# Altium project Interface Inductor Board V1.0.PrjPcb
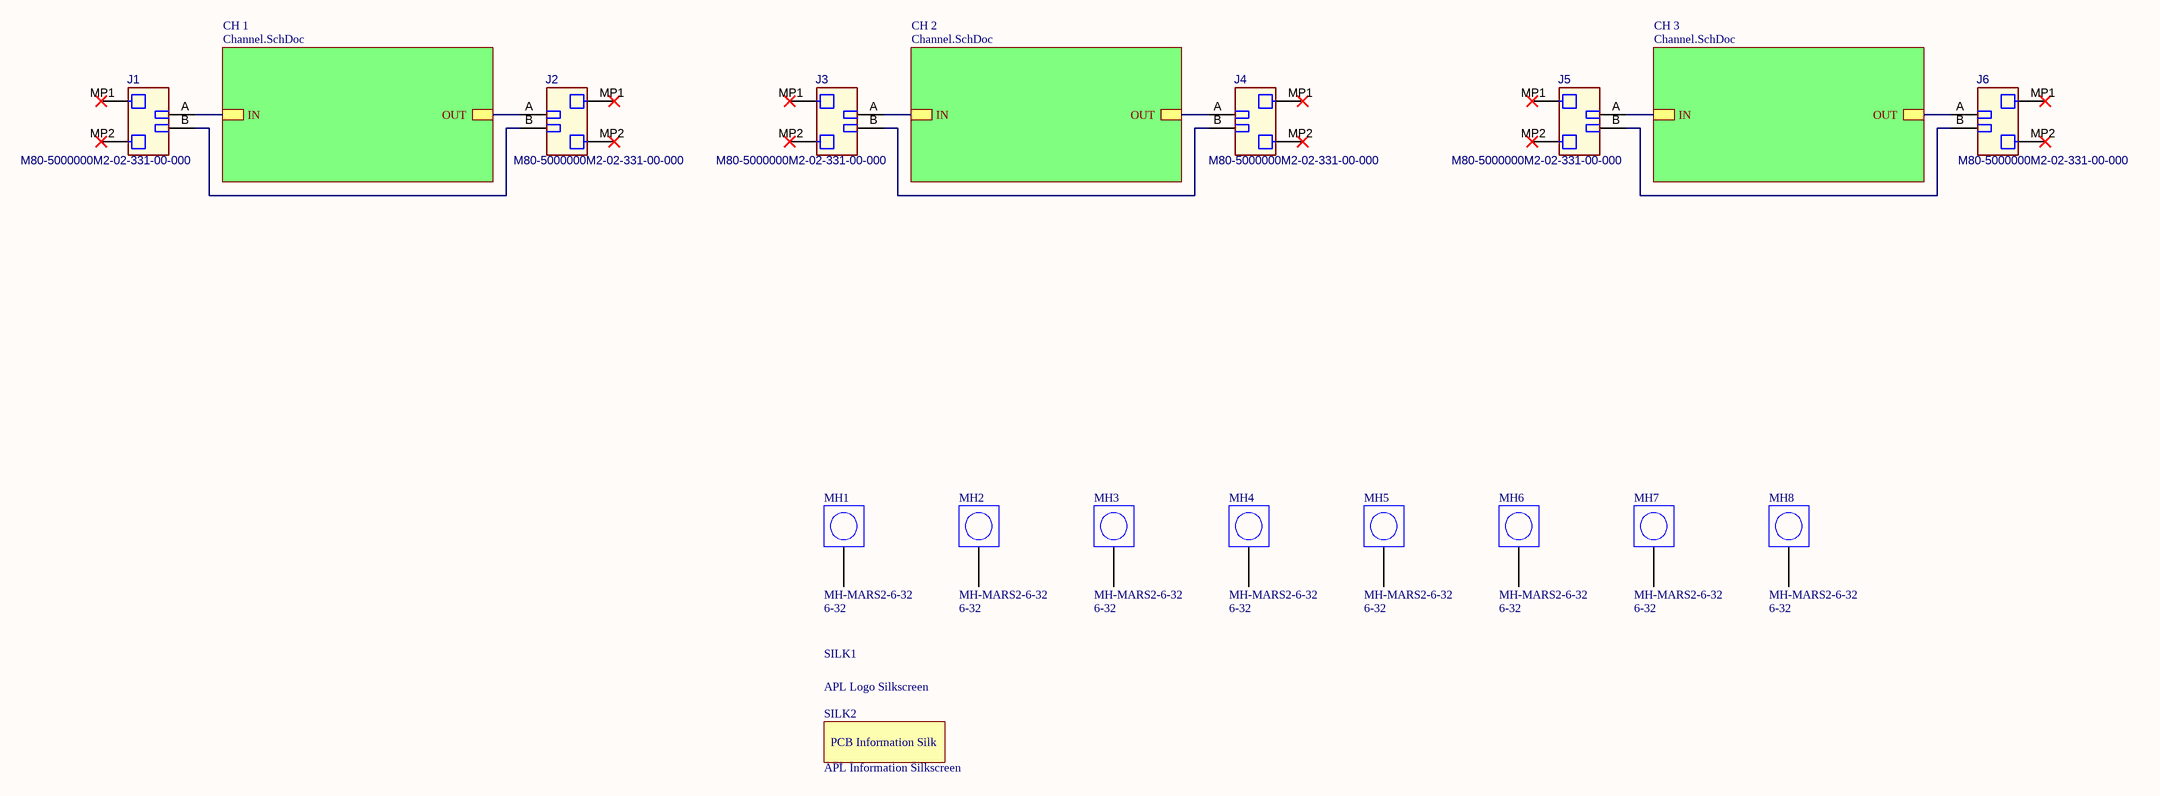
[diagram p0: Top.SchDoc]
Gbl_Cage: 98514; Gbl_CheckedBy: BSALMI; GBL_CHK_APP_DATE: 2024-09-23; Gbl_DOC_NO_ASSY_DWG: 94024; Gbl_DOC_NO_BOM: 94026; Gbl_DOC_NO_FAB_DWG: 94025; Gbl_DOC_NO_SCH_DWG: 94022; Gbl_DrawnBy: BSALMI; Gbl_DSN_APP_DATE: 2024-09-23; Gbl_ENG_APP_DATE: 2024-09-23; Gbl_Engineer: BSALMI; Gbl_PCB_DWG_NO: 94023; Gbl_Project: MARS2 LVPS; Gbl_Revision: 1.0; GLOBAL_CAGE: 98514; GLOBAL_PROJECT: MARS2 LVPS; GLOBAL_REVISION: 1.0; GLOBAL_SCH_NUM: 94022
2 sheets, 28 parts. Net scope: hierarchical (ports join the sheet entries above them; power ports are global).
Board file: PCB1.PcbDoc
Sheets:
  Top.SchDoc
    CH 1 = Channel.SchDoc
    CH 2 = Channel.SchDoc
    CH 3 = Channel.SchDoc

## Sheet Top.SchDoc: Interface Inductor Board
size 431 x 279 mm; Address1: APPLIED PHYSICS LAB; Address2: UNIVERSITY OF WASHINGTON; Address3: 1013 NE 40TH STREET; Address4: SEATTLE, WA 98105; SheetNumber: 1; SheetTotal: 2; ENG_APP_DATE: --/--/--; DSN_APP_DATE: --/--/--; CHK_APP_DATE: --/--/--

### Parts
J1  M80-5000000M2-02-331-00-000  [M80-5000000M2-02-331-00-000-Footprint-1]
J2  M80-5000000M2-02-331-00-000  [M80-5000000M2-02-331-00-000-Footprint-1]
J3  M80-5000000M2-02-331-00-000  [M80-5000000M2-02-331-00-000-Footprint-1]
J4  M80-5000000M2-02-331-00-000  [M80-5000000M2-02-331-00-000-Footprint-1]
J5  M80-5000000M2-02-331-00-000  [M80-5000000M2-02-331-00-000-Footprint-1]
J6  M80-5000000M2-02-331-00-000  [M80-5000000M2-02-331-00-000-Footprint-1]
MH1  MH-MARS2-6-32  Fastener Size: 6-32  [MH-M3-Footprint-1]  (no BOM)
MH2  MH-MARS2-6-32  Fastener Size: 6-32  [MH-M3-Footprint-1]  (no BOM)
MH3  MH-MARS2-6-32  Fastener Size: 6-32  [MH-M3-Footprint-1]  (no BOM)
MH4  MH-MARS2-6-32  Fastener Size: 6-32  [MH-M3-Footprint-1]  (no BOM)
MH5  MH-MARS2-6-32  Fastener Size: 6-32  [MH-M3-Footprint-1]  (no BOM)
MH6  MH-MARS2-6-32  Fastener Size: 6-32  [MH-M3-Footprint-1]  (no BOM)
MH7  MH-MARS2-6-32  Fastener Size: 6-32  [MH-M3-Footprint-1]  (no BOM)
MH8  MH-MARS2-6-32  Fastener Size: 6-32  [MH-M3-Footprint-1]  (no BOM)
SILK1  APL Logo Silkscreen  [APL Logo Silkscreen-Footprint-1]  (no BOM)
SILK2  APL Information Silkscreen  [APL Information Silk]  (no BOM)

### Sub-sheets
CH 1 = Channel.SchDoc: OUT, IN
CH 2 = Channel.SchDoc: OUT, IN
CH 3 = Channel.SchDoc: OUT, IN

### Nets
NetJ1_A: J1.A ; sheet CH 1/IN
NetJ1_B: J1.B J2.B
NetJ2_A: J2.A ; sheet CH 1/OUT
NetJ3_A: J3.A ; sheet CH 2/IN
NetJ3_B: J3.B J4.B
NetJ4_A: J4.A ; sheet CH 2/OUT
NetJ5_A: J5.A ; sheet CH 3/IN
NetJ5_B: J5.B J6.B
NetJ6_A: J6.A ; sheet CH 3/OUT

Not connected (* = marked no-connect by the designer): J1 MP1* MP2*; J2 MP1* MP2*; J3 MP1* MP2*; J4 MP1* MP2*; J5 MP1* MP2*; J6 MP1* MP2*; MH1 1; MH2 1; MH3 1; MH4 1; MH5 1; MH6 1; MH7 1; MH8 1

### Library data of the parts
J1-J6 = CMP-002-00145-6: Conn Datamate M 2Power POS 4mm Solder ST Thru-Hole Tube; Manufacturer: Harwin; Number of Positions: 2; Pitch: 0.157inch; Connector Type: Header; Current Rating: 20A; Voltage Rating: 800V; Gender: Male; Mated Stacking Heights: 9.75mm
MH1-MH8 = CMP-00028-00015-2: MARS2 Project 6-32 Mounting Hole Plated .; Plated: Yes
SILK1 = CMP-001-0033-3
SILK2 = CMP-001-0034-1: Text/Box for silkscreen display of PCB information.

## Sheet Channel.SchDoc
size 431 x 279 mm; Organization: ORGANIZATION; Address1: APPLIED PHYSICS LAB; Address2: UNIVERSITY OF WASHINGTON; Address3: 1013 NE 40TH STREET; Address4: SEATTLE, WA 98105; SheetTitle: Inductor Channel; Revision: -; SheetNumber: 2; SheetTotal: 2; ENG_APP_DATE: --/--/--; DSN_APP_DATE: --/--/--; CHK_APP_DATE: --/--/--
Used 3 times, as channels CH 1, CH 2, CH 3. Parts and nets are listed once, with the designators drawn on the sheet.
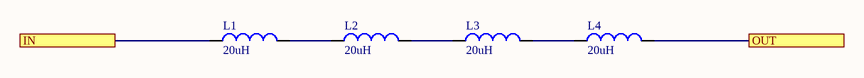
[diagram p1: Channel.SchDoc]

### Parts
L1  Inductance: 20uH  [ED0006-AL-Footprint-1]  (hidden comment: ED0006-AL)
L2  Inductance: 20uH  [ED0006-AL-Footprint-1]  (hidden comment: ED0006-AL)
L3  Inductance: 20uH  [ED0006-AL-Footprint-1]  (hidden comment: ED0006-AL)
L4  Inductance: 20uH  [ED0006-AL-Footprint-1]  (hidden comment: ED0006-AL)

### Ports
IN, OUT

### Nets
IN: L1.1 ; port IN
OUT: L4.2 ; port OUT
NetL1_2: L1.2 L2.1
NetL2_2: L2.2 L3.1
NetL3_2: L3.2 L4.1

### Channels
CH 1: designators end in _CH_1; ports IN=NetJ1_A OUT=NetJ2_A
CH 2: designators end in _CH_2; ports IN=NetJ3_A OUT=NetJ4_A
CH 3: designators end in _CH_3; ports IN=NetJ5_A OUT=NetJ6_A

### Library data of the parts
L1-L4 = CMP-006-00101-2: Power inductor, 20uH Toroidal, 20% tol, RoHS; Manufacturer: CoilCraft; Self Resonant Frequency: 13MHz; DC Resistance (DCR): 42mOhms; Decade: 10uH; Saturation Current: 36.0; Shielding: No; Q Factor: Unknown; Core Material: Ferrite; Current Rating: 7.2A

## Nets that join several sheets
NetJ1_A: Top (J1.A), CH 1 (L1_CH_1.1)
NetJ2_A: Top (J2.A), CH 1 (L4_CH_1.2)
NetJ3_A: Top (J3.A), CH 2 (L1_CH_2.1)
NetJ4_A: Top (J4.A), CH 2 (L4_CH_2.2)
NetJ5_A: Top (J5.A), CH 3 (L1_CH_3.1)
NetJ6_A: Top (J6.A), CH 3 (L4_CH_3.2)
